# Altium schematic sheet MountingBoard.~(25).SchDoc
size Legal; Organization: Altium Limited; Address1: 3 Minna Close; Address2: Belrose; Address3: NSW 2085; Address4: Australia
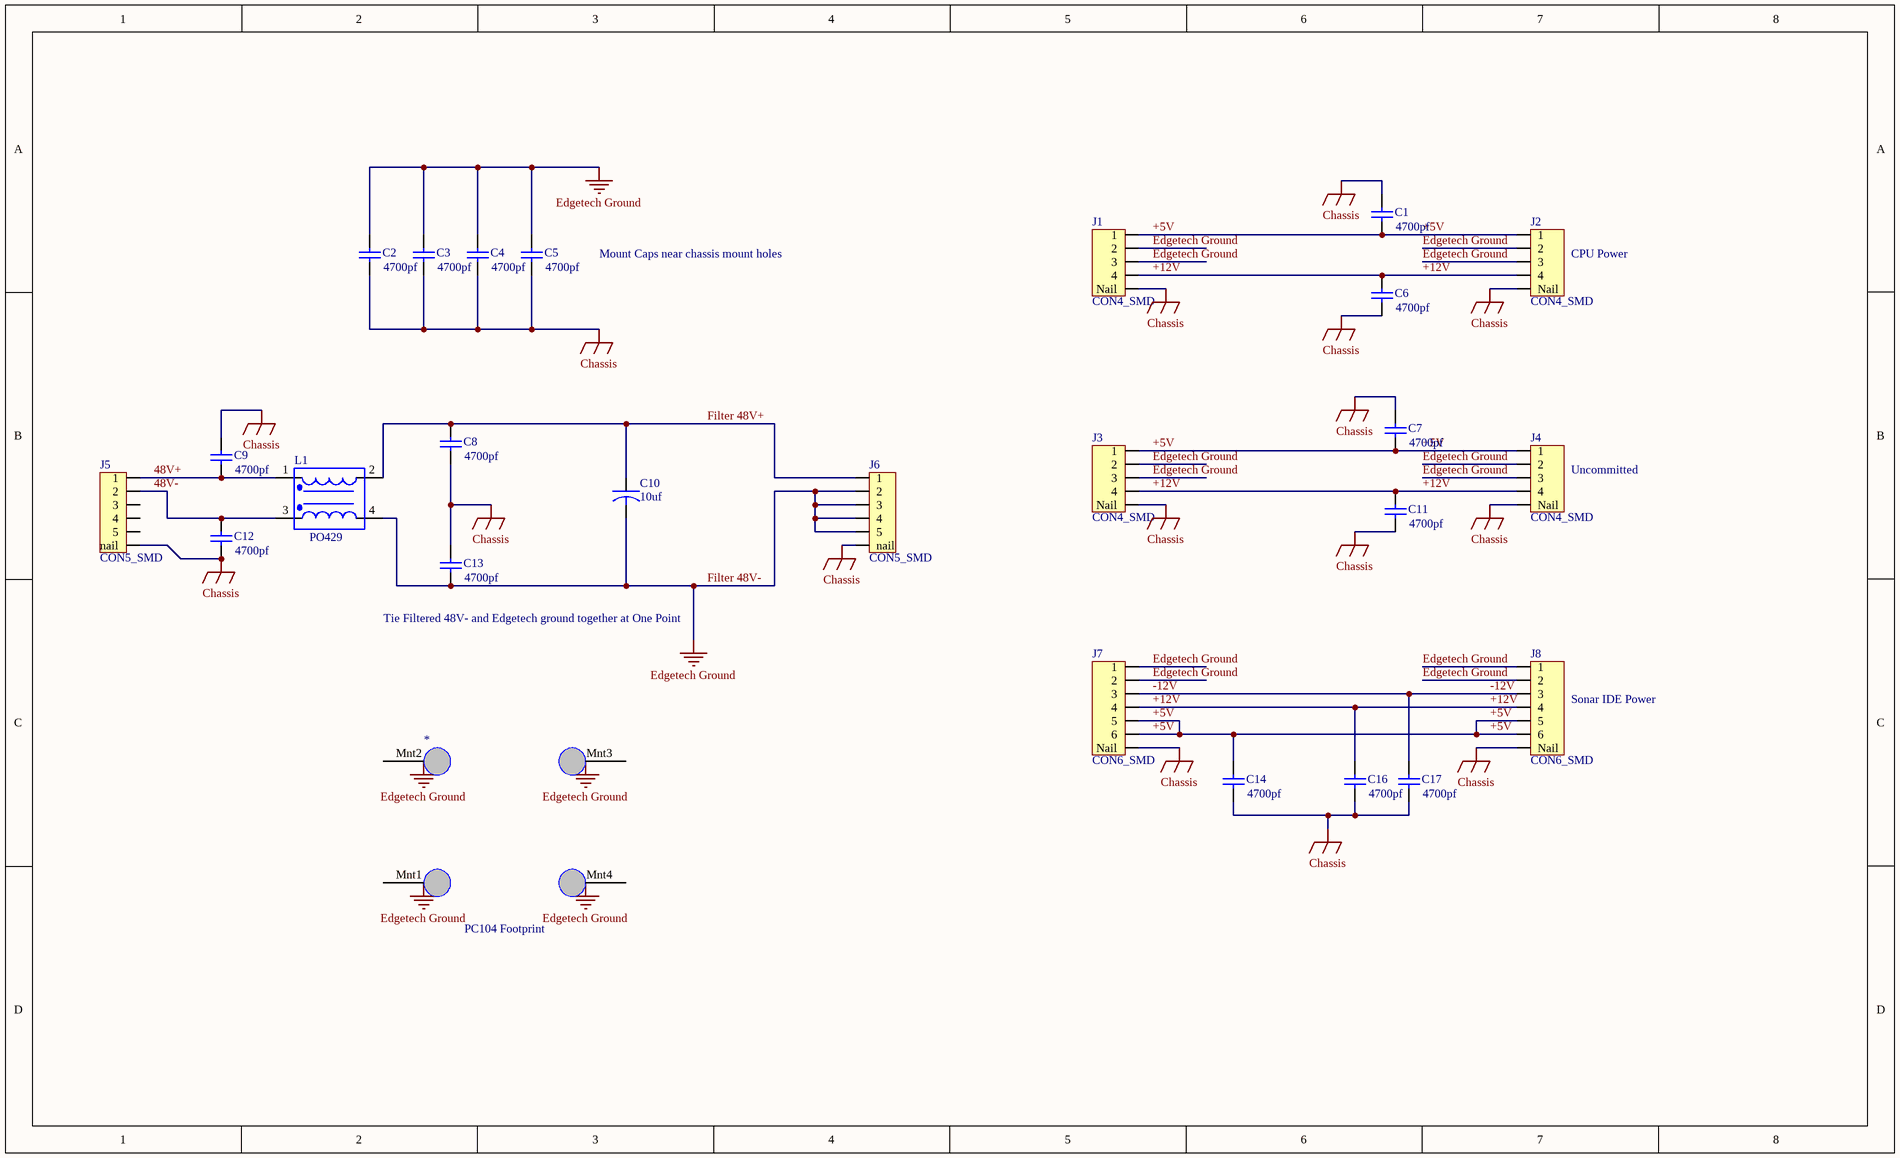
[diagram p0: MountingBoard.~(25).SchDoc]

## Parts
*  PC104 Footprint  [PC104 Footprint]
C1  value 4700pf  [7163]  (hidden comment: Cap Semi)
C2  value 4700pf  [7163]  (hidden comment: Cap Semi)
C3  value 4700pf  [7163]  (hidden comment: Cap Semi)
C4  value 4700pf  [7163]  (hidden comment: Cap Semi)
C5  value 4700pf  [7163]  (hidden comment: Cap Semi)
C6  value 4700pf  [7163]  (hidden comment: Cap Semi)
C7  value 4700pf  [7163]  (hidden comment: Cap Semi)
C8  value 4700pf  [7163]  (hidden comment: Cap Semi)
C9  value 4700pf  [7163]  (hidden comment: Cap Semi)
C10  10uf  [CAPSTICK-CS4-7-SMD]
C11  value 4700pf  [7163]  (hidden comment: Cap Semi)
C12  value 4700pf  [7163]  (hidden comment: Cap Semi)
C13  value 4700pf  [7163]  (hidden comment: Cap Semi)
C14  value 4700pf  [7163]  (hidden comment: Cap Semi)
C16  value 4700pf  [7163]  (hidden comment: Cap Semi)
C17  value 4700pf  [7163]  (hidden comment: Cap Semi)
J1  CON4_SMD  [Microfit3-1x4 SMT RA Nail]
J2  CON4_SMD  [Microfit3-1x4 SMT RA Nail]
J3  CON4_SMD  [Microfit3-1x4 SMT RA Nail]
J4  CON4_SMD  [Microfit3-1x4 SMT RA Nail]
J5  CON5_SMD  [Microfit3-1x5 SMT RA Nail]
J6  CON5_SMD  [Microfit3-1x5 SMT RA Nail]
J7  CON6_SMD  [Microfit3-1x6 SMT RA Nail]
J8  CON6_SMD  [Microfit3-1x6 SMT RA Nail]
L1  ManufPartNo: PO429  [Pulse_BigFoot]

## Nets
Chassis: C1.2 C2.1 C3.1 C4.1 C5.1 C6.1 C7.2 C8.1 C9.2 C11.1 C12.1 C13.2 C14.1 C16.1 C17.1 J1.nail(Nail) J2.nail(Nail) J3.nail(Nail) J4.nail(Nail) J5.nail J6.nail J7.Nail J8.Nail
Edgetech Ground: *.Mnt1 *.Mnt2 *.Mnt3 *.Mnt4 C2.2 C3.2 C4.2 C5.2 C10.2 C13.1 J1.2 J1.3 J2.2 J2.3 J3.2 J3.3 J4.2 J4.3 J6.2 J6.3 J6.4 J6.5 J7.1 J7.2 J8.1 J8.2 L1.4  [also labelled Filter 48V-]
48V+: C9.1 J5.1 L1.1
48V-: C12.2 J5.2 L1.3
+5V: C1.1 C7.1 C14.2 J1.1 J2.1 J3.1 J4.1 J7.5 J7.6 J8.5 J8.6
+12V: C6.2 C11.2 C16.2 J1.4 J2.4 J3.4 J4.4 J7.4 J8.4
-12V: C17.2 J7.3 J8.3
Filter 48V+: C8.2 C10.1 J6.1 L1.2

Not connected (* = marked no-connect by the designer): J5 3 4 5

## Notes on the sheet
- Mount Caps near chassis mount holes
- (near J2) CPU Power
- (near J4) Uncommitted
- (near C13) Tie Filtered 48V- and Edgetech ground together at One Point
- (near J8) Sonar IDE Power

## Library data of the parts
C1-C9 C11-C14 C16 C17 = Cap Semi: Capacitor (Semiconductor SIM Model); Manufacturer: Panasonic; ManufPartNo: ECK-TBC472MF; VendorPartNo: P10743TR-ND; Vendor: Digikey
C10 = CAPACITOR: ManufPartNo: 106K100CS4G; Manufacturer: ITW Paktron; Vendor: Future Electronics; Value: 10
J1-J4 = CON4_SMD: Manufacturer: Molex; ManufPartNo: 43650-0412; VendorPartNo: WM1892-ND; Vendor: Digikey
J5 J6 = CON5_SMD: Connector; Manufacturer: Molex; ManufPartNo: 43650-0512; VendorPartNo: WM1893-ND; Vendor: Digikey
J7 = CON6_SMD: Manufacturer: Molex; ManufPartNo: 43650-0612; VendorPartNo: WM1894-ND; Vendor: Digikey
L1 = COMMON MODE CHOKE: Manufacturer: Pulse Engineering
